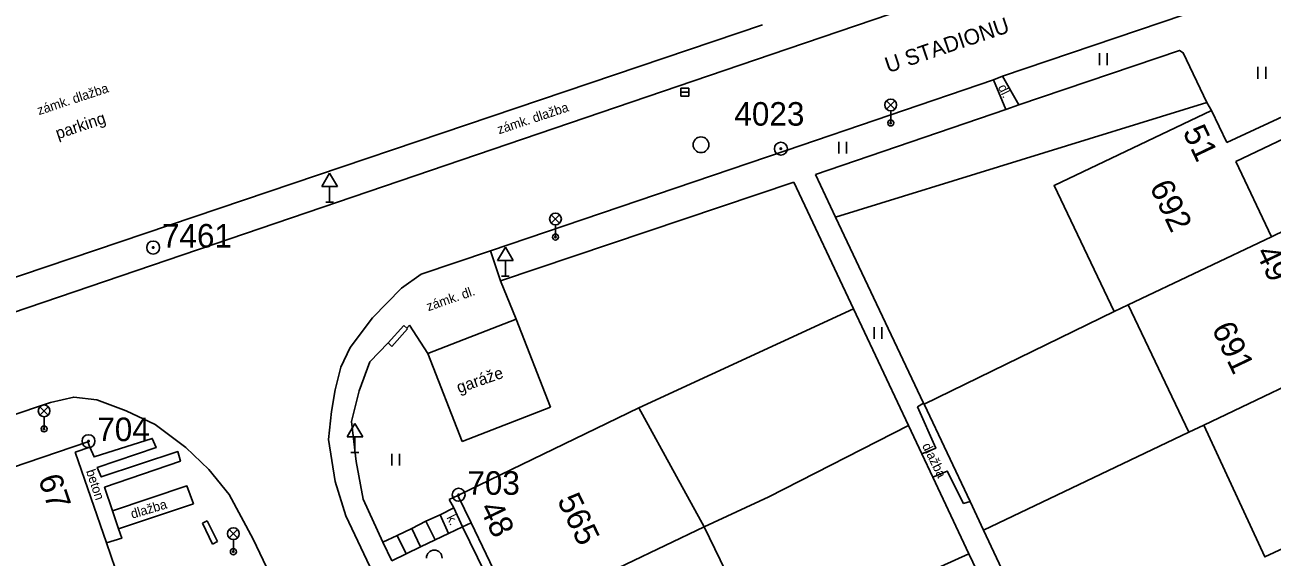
# Model space of a CAD drawing. Extents: x -493753 to -49290, y -1127285 to -112654.
# Drawn here: x -493226.3 to -493146.9, y -1127042.8 to -1127008.9 of the extents above; entities that cross this region are included whole.
import ezdxf

# ---------------------------------------------------------------- set-up
doc = ezdxf.new("R2010")
doc.units = 0
for name, color, linetype in [('Vrstva 10', 7, 'Continuous'), ('Vrstva 11', 7, 'Continuous'), ('Vrstva 22', 7, 'Continuous'), ('Vrstva 24', 7, 'Continuous'), ('Vrstva 27', 7, 'Continuous'), ('Vrstva 33', 7, 'Continuous'), ('Vrstva 34', 7, 'Continuous'), ('Vrstva 36', 7, 'Continuous'), ('Vrstva 40', 7, 'Continuous'), ('Vrstva 41', 7, 'Continuous'), ('Vrstva 42', 7, 'Continuous'), ('Vrstva 43', 7, 'Continuous'), ('Vrstva 44', 7, 'Continuous'), ('Vrstva 45', 7, 'Continuous'), ('Vrstva 5', 7, 'Continuous'), ('Vrstva 63', 7, 'Continuous'), ('Vrstva 7', 7, 'Continuous'), ('Vrstva 8', 7, 'Continuous')]:
    doc.layers.add(name, color=color, linetype=linetype)

msp = doc.modelspace()

# ---------------------------------------------------------------- linework, layer by layer
at = {"layer": 'Vrstva 10'}
for p, q in [((-493136.98, -1126996.52), (-493178.78, -1127010.77)), ((-493178.78, -1127010.77), (-493238.52, -1127031.13)), ((-493201.09, -1127024.78), (-493196.68, -1127023.28)), ((-493201.09, -1127024.78), (-493202.34, -1127025.68)), ((-493203.19, -1127029.16), (-493204.35, -1127030.37)), ((-493204.79, -1127039.12), (-493203.53, -1127041.87)), ((-493205.89, -1127040.18), (-493179.72, -1127095.23))]:
    msp.add_line(p, q, dxfattribs=at)
for points in [[(-493164.05, -1127012.15), (-493151.05, -1127007.76), (-493148.12, -1127006.88), (-493147.14, -1127006.61)], [(-493164.63, -1127012.39), (-493164.05, -1127012.15)], [(-493164.05, -1127012.15), (-493163.02, -1127013.99)], [(-493177.83, -1127016.89), (-493164.63, -1127012.39)], [(-493164.63, -1127012.39), (-493163.84, -1127014.28)], [(-493196.68, -1127023.28), (-493177.83, -1127016.89)], [(-493196.68, -1127023.28), (-493196.03, -1127025.21)], [(-493205.62, -1127029.45), (-493204.18, -1127027.57), (-493202.34, -1127025.68)], [(-493206.99, -1127035.31), (-493206.81, -1127033.54), (-493206.57, -1127032.16), (-493206.21, -1127030.71), (-493205.62, -1127029.45)], [(-493204.35, -1127030.37), (-493205.03, -1127032.21), (-493205.52, -1127034.17)], [(-493260.05, -1127044.84), (-493224.71, -1127032.96), (-493223.22, -1127032.61), (-493221.74, -1127032.78), (-493219.88, -1127033.49), (-493218.04, -1127034.37), (-493216.09, -1127035.82), (-493214.61, -1127037.23), (-493213.32, -1127038.83), (-493211.79, -1127041.66), (-493209.65, -1127046.18), (-493209.2, -1127047.13), (-493207.05, -1127051.66)], [(-493169.18, -1127036.24), (-493168.3, -1127035.87), (-493169.46, -1127033.24), (-493169.09, -1127032.99)], [(-493205.52, -1127034.17), (-493205.22, -1127036.71), (-493204.79, -1127039.12)], [(-493220.75, -1127039.87), (-493221.26, -1127038.36), (-493216.42, -1127036.69), (-493216.59, -1127036.09), (-493221.47, -1127037.7), (-493221.72, -1127037.11), (-493217.98, -1127035.83), (-493218.22, -1127035.25), (-493221.92, -1127036.43), (-493222.19, -1127035.81)], [(-493205.89, -1127040.18), (-493206.57, -1127038), (-493206.99, -1127035.31)], [(-493166.12, -1127039.26), (-493166.53, -1127039.39), (-493167.57, -1127037.33), (-493168.49, -1127037.71)], [(-493215.59, -1127039.41), (-493216.01, -1127038.27), (-493220.75, -1127039.87)], [(-493199.31, -1127039.14), (-493198.75, -1127038.88)], [(-493199, -1127039.68), (-493199.31, -1127039.14)], [(-493215.59, -1127039.41), (-493220.36, -1127041.01)], [(-493199.87, -1127040.11), (-493199, -1127039.68)], [(-493201.69, -1127040.98), (-493200.8, -1127040.53)], [(-493200.8, -1127040.53), (-493199.87, -1127040.11)], [(-493199.35, -1127041.31), (-493198.46, -1127040.88), (-493197.91, -1127040.62)], [(-493221.14, -1127041.9), (-493220.16, -1127041.61), (-493220.36, -1127041.01)], [(-493203.53, -1127041.87), (-493202.62, -1127041.43)], [(-493202.62, -1127041.43), (-493201.69, -1127040.98)], [(-493198.46, -1127040.88), (-493197.04, -1127043.79), (-493200.63, -1127045.49), (-493201.67, -1127045.75)], [(-493200.19, -1127041.71), (-493199.35, -1127041.31)], [(-493202.05, -1127042.6), (-493201.12, -1127042.16)], [(-493201.12, -1127042.16), (-493200.19, -1127041.71)], [(-493202.96, -1127043.04), (-493202.05, -1127042.6)]]:
    msp.add_lwpolyline(points, dxfattribs=at)
at = {"layer": 'Vrstva 11'}
for p, q in [((-493236.39, -1127028.17), (-493179.35, -1127008.88)), ((-493202.96, -1127043.04), (-493203.53, -1127041.87))]:
    msp.add_line(p, q, dxfattribs=at)
for points in [[(-493174.68, -1127021.14), (-493151.04, -1127013.84)], [(-493187.22, -1127033.3), (-493173.54, -1127026.98)], [(-493184.82, -1127037.68), (-493183.06, -1127040.88)], [(-493183.06, -1127040.88), (-493178.94, -1127038.97)], [(-493220.36, -1127041.01), (-493220.75, -1127039.87)], [(-493199, -1127039.68), (-493198.46, -1127040.88)], [(-493200.8, -1127040.53), (-493200.19, -1127041.71)], [(-493199.87, -1127040.11), (-493199.35, -1127041.31)], [(-493202.62, -1127041.43), (-493202.05, -1127042.6)], [(-493201.69, -1127040.98), (-493201.12, -1127042.16)], [(-493183.06, -1127040.88), (-493190.52, -1127044.45)], [(-493183.06, -1127040.88), (-493179.33, -1127048.6)]]:
    msp.add_lwpolyline(points, dxfattribs=at)
at = {"layer": 'Vrstva 22'}
msp.add_arc((-493200.25, -1127042.87), 0.5, 360, 180, dxfattribs=at)
at = {"layer": 'Vrstva 24'}
for p, q in [((-493203.19, -1127029.16), (-493202.19, -1127028.05)), ((-493201.96, -1127028.27), (-493202.96, -1127029.38)), ((-493202.96, -1127029.38), (-493203.19, -1127029.16)), ((-493215.01, -1127040.65), (-493214.73, -1127040.51)), ((-493214.39, -1127041.99), (-493215.01, -1127040.65)), ((-493214.73, -1127040.51), (-493214.07, -1127041.82)), ((-493214.07, -1127041.82), (-493214.39, -1127041.99))]:
    msp.add_line(p, q, dxfattribs=at)
msp.add_lwpolyline([(-493202.19, -1127028.05), (-493202.01, -1127028.22), (-493201.96, -1127028.27)], dxfattribs=at)
at = {"layer": 'Vrstva 27'}
msp.add_line((-493184.54, -1127013.18), (-493184.04, -1127013.18), dxfattribs=at)
msp.add_lwpolyline([(-493184.54, -1127013.43), (-493184.04, -1127013.43), (-493184.04, -1127012.93), (-493184.54, -1127012.93)], close=True, dxfattribs=at)
msp.add_circle((-493183.26, -1127016.53), 0.5, dxfattribs=at)
at = {"layer": 'Vrstva 33'}
for p, q in [((-493171.435, -1127013.725), (-493170.905, -1127014.255)), ((-493171.435, -1127014.255), (-493170.905, -1127013.725)), ((-493171.17, -1127015.14), (-493171.17, -1127014.365)), ((-493192.795, -1127020.995), (-493192.265, -1127021.525)), ((-493192.795, -1127021.525), (-493192.265, -1127020.995)), ((-493192.53, -1127022.41), (-493192.53, -1127021.635)), ((-493225.375, -1127033.225), (-493224.845, -1127033.755)), ((-493225.375, -1127033.755), (-493224.845, -1127033.225)), ((-493225.11, -1127034.64), (-493225.11, -1127033.865)), ((-493213.315, -1127041.055), (-493212.785, -1127041.585)), ((-493213.315, -1127041.585), (-493212.785, -1127041.055)), ((-493213.05, -1127042.47), (-493213.05, -1127041.695))]:
    msp.add_line(p, q, dxfattribs=at)
for centre, radius in [((-493171.17, -1127013.99), 0.375), ((-493171.17, -1127015.14), 0.19), ((-493171.17, -1127015.14), 0.05), ((-493192.53, -1127021.26), 0.375), ((-493192.53, -1127022.41), 0.19), ((-493192.53, -1127022.41), 0.05), ((-493225.11, -1127033.49), 0.375), ((-493225.11, -1127034.64), 0.19), ((-493225.11, -1127034.64), 0.05), ((-493213.05, -1127041.32), 0.375), ((-493213.05, -1127042.47), 0.19), ((-493213.05, -1127042.47), 0.05)]:
    msp.add_circle(centre, radius, dxfattribs=at)
at = {"layer": 'Vrstva 34'}
for p, q in [((-493207.42, -1127019.19), (-493206.92, -1127018.34)), ((-493206.92, -1127018.34), (-493206.42, -1127019.19)), ((-493207.42, -1127019.19), (-493206.42, -1127019.19)), ((-493206.92, -1127020.19), (-493206.92, -1127019.19)), ((-493207.17, -1127020.19), (-493206.67, -1127020.19)), ((-493196.22, -1127023.9), (-493195.72, -1127023.05)), ((-493195.72, -1127023.05), (-493195.22, -1127023.9)), ((-493196.22, -1127023.9), (-493195.22, -1127023.9)), ((-493195.72, -1127024.9), (-493195.72, -1127023.9)), ((-493195.97, -1127024.9), (-493195.47, -1127024.9)), ((-493205.81, -1127035.15), (-493205.31, -1127034.3)), ((-493205.31, -1127034.3), (-493204.81, -1127035.15)), ((-493205.81, -1127035.15), (-493204.81, -1127035.15)), ((-493205.31, -1127036.15), (-493205.31, -1127035.15)), ((-493205.56, -1127036.15), (-493205.06, -1127036.15))]:
    msp.add_line(p, q, dxfattribs=at)
at = {"layer": 'Vrstva 36'}
for p, q in [((-493157.88, -1127011.45), (-493157.88, -1127010.7)), ((-493157.38, -1127011.45), (-493157.38, -1127010.7)), ((-493147.78, -1127012.32), (-493147.78, -1127011.57)), ((-493147.28, -1127012.32), (-493147.28, -1127011.57)), ((-493174.48, -1127017.09), (-493174.48, -1127016.34)), ((-493173.98, -1127017.09), (-493173.98, -1127016.34)), ((-493172.23, -1127028.9), (-493172.23, -1127028.15)), ((-493171.73, -1127028.9), (-493171.73, -1127028.15)), ((-493202.96, -1127036.98), (-493202.96, -1127036.23)), ((-493202.46, -1127036.98), (-493202.46, -1127036.23))]:
    msp.add_line(p, q, dxfattribs=at)
at = {"layer": 'Vrstva 5'}
for p, q in [((-493192.84, -1127033.25), (-493195.03, -1127027.64)), ((-493198.47, -1127035.45), (-493192.84, -1127033.25)), ((-493184.82, -1127037.68), (-493187.22, -1127033.3)), ((-493236.71, -1127040.37), (-493222.32, -1127035.47)), ((-493222.19, -1127035.81), (-493223.12, -1127036.13)), ((-493222.32, -1127035.47), (-493222.19, -1127035.81))]:
    msp.add_line(p, q, dxfattribs=at)
for points in [[(-493149.76, -1127016.39), (-493150.74, -1127014.35), (-493160.76, -1127019.12), (-493156.93, -1127027.16), (-493156.04, -1127026.74)], [(-493149.19, -1127017.59), (-493144.76, -1127015.5), (-493145.32, -1127014.32), (-493149.76, -1127016.39)], [(-493146.91, -1127022.39), (-493149.19, -1127017.59)], [(-493156.04, -1127026.74), (-493146.91, -1127022.39)], [(-493146.91, -1127022.39), (-493146.01, -1127021.96), (-493145.97, -1127022.06), (-493144.75, -1127024.62), (-493144.16, -1127025.85), (-493143.43, -1127027.38), (-493142.15, -1127030.07)], [(-493151.23, -1127034.4), (-493152.17, -1127034.85), (-493156.04, -1127026.74)], [(-493198.47, -1127035.45), (-493200.66, -1127029.84), (-493195.03, -1127027.64)], [(-493151.23, -1127034.4), (-493147.34, -1127042.8), (-493137.27, -1127038.13), (-493138.77, -1127034.89), (-493139.43, -1127033.47), (-493140.01, -1127032.21), (-493141.18, -1127029.68), (-493141.22, -1127029.6), (-493142.15, -1127030.07)], [(-493142.15, -1127030.07), (-493151.23, -1127034.4)], [(-493195.03, -1127046.62), (-493197.91, -1127040.62), (-493198.75, -1127038.88), (-493187.22, -1127033.3)], [(-493223.12, -1127036.13), (-493221.14, -1127041.9), (-493220.03, -1127045.14)]]:
    msp.add_lwpolyline(points, dxfattribs=at)
at = {"layer": 'Vrstva 63'}
for centre, radius in [((-493178.17, -1127016.78), 0.412), ((-493178.17, -1127016.78), 0.05), ((-493218.16, -1127023.08), 0.412), ((-493218.16, -1127023.08), 0.05), ((-493222.28, -1127035.42), 0.412), ((-493222.28, -1127035.42), 0.05), ((-493198.7, -1127038.84), 0.412), ((-493198.7, -1127038.84), 0.05)]:
    msp.add_circle(centre, radius, dxfattribs=at)
at = {"layer": 'Vrstva 7'}
for p, q in [((-493195.03, -1127027.64), (-493196.03, -1127025.21)), ((-493169.05, -1127033.07), (-493156.93, -1127027.16)), ((-493201.82, -1127028.03), (-493200.66, -1127029.84)), ((-493178.94, -1127038.97), (-493170.03, -1127034.42)), ((-493165.26, -1127041.09), (-493152.17, -1127034.85)), ((-493175.32, -1127046.71), (-493166.2, -1127042.6))]:
    msp.add_line(p, q, dxfattribs=at)
for points in [[(-493163.02, -1127013.99), (-493152.78, -1127010.51), (-493152.54, -1127010.66), (-493151.04, -1127013.84), (-493150.74, -1127014.35)], [(-493175.96, -1127018.42), (-493163.84, -1127014.28)], [(-493169.05, -1127033.07), (-493169.09, -1127032.99), (-493174.68, -1127021.14), (-493175.96, -1127018.42)], [(-493196.03, -1127025.21), (-493177.34, -1127018.91)], [(-493177.34, -1127018.91), (-493173.54, -1127026.98), (-493170.03, -1127034.42), (-493169.18, -1127036.24), (-493168.49, -1127037.71), (-493166.2, -1127042.6), (-493162.56, -1127050.16)], [(-493202.01, -1127028.22), (-493201.82, -1127028.03)], [(-493152.8, -1127067.49), (-493156.73, -1127059.26), (-493160.63, -1127050.95), (-493165.26, -1127041.09), (-493166.12, -1127039.26), (-493169.05, -1127033.07)]]:
    msp.add_lwpolyline(points, dxfattribs=at)
at = {"layer": 'Vrstva 8'}
msp.add_lwpolyline([(-493163.84, -1127014.28), (-493163.02, -1127013.99)], dxfattribs=at)

# ---------------------------------------------------------------- texts
at = {"layer": 'Vrstva 40'}
for s, rotation, p in [('zámk. dlažba', 18.30186, (-493225.435, -1127014.645)), ('dl.', 295.94804, (-493164.358, -1127012.854)), ('zámk. dlažba', 18.30186, (-493196.125, -1127015.865)), ('zámk. dl.', 19.09372, (-493200.632, -1127027.143)), ('dlažba', 296.22456, (-493169.188, -1127035.708)), ('beton', 288.46824, (-493222.447, -1127037.33)), ('dlažba', 16.59269, (-493219.491, -1127040.368)), ('k.', 296.51451, (-493199.49, -1127040.29))]:
    msp.add_text(s, height=0.6, rotation=rotation, dxfattribs=at).set_placement(p)
at = {"layer": 'Vrstva 41'}
msp.add_text('garáže', height=0.75, rotation=19.33401, dxfattribs=at).set_placement((-493198.675, -1127032.378))
at = {"layer": 'Vrstva 42'}
msp.add_text('parking', height=0.75, rotation=18.6847, dxfattribs=at).set_placement((-493224.232, -1127016.183))
at = {"layer": 'Vrstva 43'}
for s, rotation, p in [('692', 295.46261, (-493154.707, -1127019.2)), ('691', 295.50032, (-493150.748, -1127028.243)), ('565', 295.67047, (-493192.448, -1127039.183))]:
    msp.add_text(s, height=1.5, rotation=rotation, dxfattribs=at).set_placement(p)
at = {"layer": 'Vrstva 44'}
for s, rotation, p in [('51', 295.46261, (-493152.595, -1127015.706)), ('49', 295.50032, (-493147.946, -1127023.383)), ('67', 288.96101, (-493225.506, -1127037.808)), ('48', 295.67047, (-493197.403, -1127039.685))]:
    msp.add_text(s, height=1.5, rotation=rotation, dxfattribs=at).set_placement(p)
at = {"layer": 'Vrstva 45'}
msp.add_text('U STADIONU', height=1, rotation=18.65943, dxfattribs=at).set_placement((-493171.336, -1127011.967))
at = {"layer": 'Vrstva 63'}
for s, p in [(' 4023', (-493181.69, -1127015.31)), (' 7461', (-493218.16, -1127023.08)), (' 704', (-493222.28, -1127035.42)), (' 703', (-493198.7, -1127038.84))]:
    msp.add_text(s, height=1.5, dxfattribs=at).set_placement(p)

doc.saveas('drawing.dxf')
